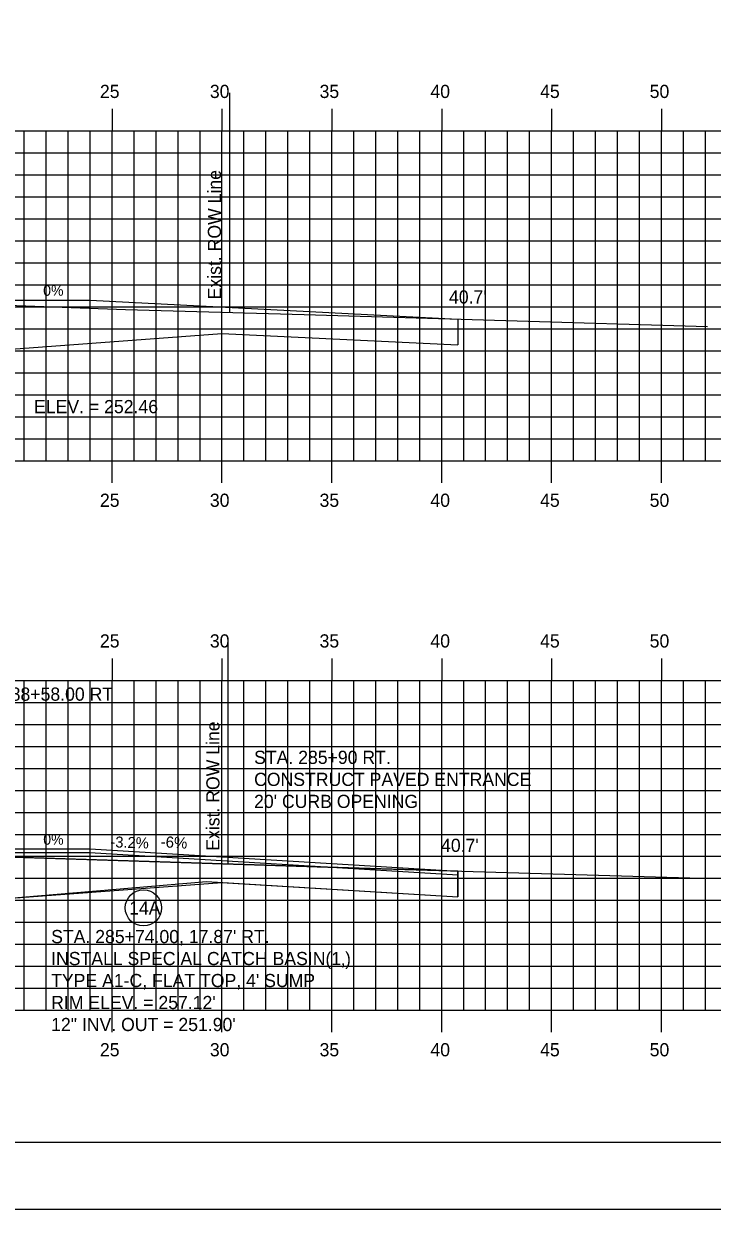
# Model space of a CAD drawing. Extents: x 856903 to 857073, y 366268 to 366378.
# Drawn here: x 857006.8 to 857038.1, y 366268.2 to 366322.1 of the extents above; entities that cross this region are included whole.
import ezdxf

# ---------------------------------------------------------------- set-up
doc = ezdxf.new("R2010")
doc.units = 0
for name, color, linetype in [('ANNOTATION', 7, 'Continuous'), ('BORDER', 7, 'Continuous'), ('D_Drainage_Text', 7, 'Continuous'), ('D_Roadway_Drive_Gravel_LT', 7, 'Continuous'), ('D_Roadway_Drive_Gravel_RT', 7, 'Continuous'), ('D_Roadway_Drive_SubGrade', 7, 'Continuous'), ('D_Text_Monospaced', 7, 'Continuous'), ('D_Text_Standard', 7, 'Continuous'), ('E_ROW_Line', 7, 'Continuous'), ('H_V ANNOTATION', 7, 'Continuous'), ('JUNK COM EXC', 7, 'Continuous'), ('MAJOR', 7, 'Continuous'), ('MINOR', 7, 'Continuous'), ('PLOT BOUNDARY', 7, 'Continuous'), ('S_Roadway_Centerline', 7, 'Continuous')]:
    doc.layers.add(name, color=color, linetype=linetype)

msp = doc.modelspace()

# ---------------------------------------------------------------- linework, layer by layer
at = {"layer": 'BORDER'}
msp.add_line((856910.784, 366271.236), (857070.784, 366271.236), dxfattribs=at)
at = {"layer": 'D_Drainage_Text'}
msp.add_circle((857012.208, 366281.891), 0.825, dxfattribs=at)
at = {"layer": 'D_Roadway_Drive_Gravel_LT'}
for p, q in [((857005.781, 366309.546), (857009.781, 366309.546)), ((857009.781, 366309.546), (857026.513, 366308.678)), ((857015.784, 366308.025), (857026.513, 366307.511)), ((857005.785, 366284.571), (857009.785, 366284.571)), ((857005.785, 366284.404), (857009.785, 366284.404)), ((857009.775, 366284.404), (857026.517, 366283.4)), ((857009.785, 366284.571), (857026.517, 366283.567)), ((857015.784, 366283.042), (857026.517, 366282.398))]:
    msp.add_line(p, q, dxfattribs=at)
at = {"layer": 'D_Roadway_Drive_SubGrade'}
for p, q in [((857026.513, 366308.678), (857026.513, 366307.511)), ((857005.781, 366307.272), (857015.784, 366308.025)), ((857005.784, 366282.297), (857015.784, 366283.042)), ((857026.517, 366283.567), (857026.517, 366282.4))]:
    msp.add_line(p, q, dxfattribs=at)
at = {"layer": 'E_ROW_Line'}
for p, q in [((857016.141, 366308.975), (857016.141, 366318.975)), ((857016.071, 366283.889), (857016.071, 366293.889))]:
    msp.add_line(p, q, dxfattribs=at)
at = {"layer": 'JUNK COM EXC'}
msp.add_lwpolyline([(857005.784, 366284.218), (857005.784, 366282.297), (857005.784, 366282.297), (857015.079, 366283.084), (857026.517, 366282.398), (857026.517, 366283.567), (857022.035, 366283.697), (857005.784, 366284.218)], dxfattribs=at)
at = {"layer": 'MAJOR'}
for p, q in [((857010.784, 366318.238), (857010.784, 366317.236)), ((857015.784, 366318.238), (857015.784, 366317.236)), ((857020.784, 366318.238), (857020.784, 366317.236)), ((857025.784, 366318.238), (857025.784, 366317.236)), ((857030.784, 366318.238), (857030.784, 366317.236)), ((857035.784, 366318.238), (857035.784, 366317.236)), ((856915.784, 366317.236), (857055.784, 366317.236)), ((856915.784, 366317.236), (857055.784, 366317.236)), ((857010.784, 366302.236), (857010.784, 366317.236)), ((857015.784, 366302.236), (857015.784, 366317.236)), ((857020.784, 366302.236), (857020.784, 366317.236)), ((857025.784, 366302.236), (857025.784, 366317.236)), ((857030.784, 366302.236), (857030.784, 366317.236)), ((857035.784, 366302.236), (857035.784, 366317.236)), ((856915.784, 366312.236), (857055.784, 366312.236)), ((856915.784, 366307.236), (857055.784, 366307.236)), ((856915.784, 366302.236), (857055.784, 366302.236)), ((856915.784, 366302.236), (857055.784, 366302.236)), ((857010.784, 366301.234), (857010.784, 366302.236)), ((857015.784, 366301.234), (857015.784, 366302.236)), ((857020.784, 366301.234), (857020.784, 366302.236)), ((857025.784, 366301.234), (857025.784, 366302.236)), ((857030.784, 366301.234), (857030.784, 366302.236)), ((857035.784, 366301.234), (857035.784, 366302.236)), ((857010.784, 366293.238), (857010.784, 366292.236)), ((857015.784, 366293.238), (857015.784, 366292.236)), ((857020.784, 366293.238), (857020.784, 366292.236)), ((857025.784, 366293.238), (857025.784, 366292.236)), ((857030.784, 366293.238), (857030.784, 366292.236)), ((857035.784, 366293.238), (857035.784, 366292.236)), ((856915.784, 366292.236), (857055.784, 366292.236)), ((856915.784, 366292.236), (857055.784, 366292.236)), ((857010.784, 366277.236), (857010.784, 366292.236)), ((857015.784, 366277.236), (857015.784, 366292.236)), ((857020.784, 366277.236), (857020.784, 366292.236)), ((857025.784, 366277.236), (857025.784, 366292.236)), ((857030.784, 366277.236), (857030.784, 366292.236)), ((857035.784, 366277.236), (857035.784, 366292.236)), ((856915.784, 366287.236), (857055.784, 366287.236)), ((856915.784, 366282.236), (857055.784, 366282.236)), ((856915.784, 366277.236), (857055.784, 366277.236)), ((856915.784, 366277.236), (857055.784, 366277.236)), ((857010.784, 366276.234), (857010.784, 366277.236)), ((857015.784, 366276.234), (857015.784, 366277.236)), ((857020.784, 366276.234), (857020.784, 366277.236)), ((857025.784, 366276.234), (857025.784, 366277.236)), ((857030.784, 366276.234), (857030.784, 366277.236)), ((857035.784, 366276.234), (857035.784, 366277.236))]:
    msp.add_line(p, q, dxfattribs=at)
at = {"layer": 'MINOR'}
for p, q in [((857006.784, 366302.236), (857006.784, 366317.236)), ((857007.784, 366302.236), (857007.784, 366317.236)), ((857008.784, 366302.236), (857008.784, 366317.236)), ((857009.784, 366302.236), (857009.784, 366317.236)), ((857011.784, 366302.236), (857011.784, 366317.236)), ((857012.784, 366302.236), (857012.784, 366317.236)), ((857013.784, 366302.236), (857013.784, 366317.236)), ((857014.784, 366302.236), (857014.784, 366317.236)), ((857016.784, 366302.236), (857016.784, 366317.236)), ((857017.784, 366302.236), (857017.784, 366317.236)), ((857018.784, 366302.236), (857018.784, 366317.236)), ((857019.784, 366302.236), (857019.784, 366317.236)), ((857021.784, 366302.236), (857021.784, 366317.236)), ((857022.784, 366302.236), (857022.784, 366317.236)), ((857023.784, 366302.236), (857023.784, 366317.236)), ((857024.784, 366302.236), (857024.784, 366317.236)), ((857026.784, 366302.236), (857026.784, 366317.236)), ((857027.784, 366302.236), (857027.784, 366317.236)), ((857028.784, 366302.236), (857028.784, 366317.236)), ((857029.784, 366302.236), (857029.784, 366317.236)), ((857031.784, 366302.236), (857031.784, 366317.236)), ((857032.784, 366302.236), (857032.784, 366317.236)), ((857033.784, 366302.236), (857033.784, 366317.236)), ((857034.784, 366302.236), (857034.784, 366317.236)), ((857036.784, 366302.236), (857036.784, 366317.236)), ((857037.784, 366302.236), (857037.784, 366317.236)), ((856915.784, 366316.236), (857055.784, 366316.236)), ((856915.784, 366315.236), (857055.784, 366315.236)), ((856915.784, 366314.236), (857055.784, 366314.236)), ((856915.784, 366313.236), (857055.784, 366313.236)), ((856915.784, 366311.236), (857055.784, 366311.236)), ((856915.784, 366310.236), (857055.784, 366310.236)), ((856915.784, 366309.236), (857055.784, 366309.236)), ((856915.784, 366308.236), (857055.784, 366308.236)), ((856915.784, 366306.236), (857055.784, 366306.236)), ((856915.784, 366305.236), (857055.784, 366305.236)), ((856915.784, 366304.236), (857055.784, 366304.236)), ((856915.784, 366303.236), (857055.784, 366303.236)), ((857006.784, 366277.236), (857006.784, 366292.236)), ((857007.784, 366277.236), (857007.784, 366292.236)), ((857008.784, 366277.236), (857008.784, 366292.236)), ((857009.784, 366277.236), (857009.784, 366292.236)), ((857011.784, 366277.236), (857011.784, 366292.236)), ((857012.784, 366277.236), (857012.784, 366292.236)), ((857013.784, 366277.236), (857013.784, 366292.236)), ((857014.784, 366277.236), (857014.784, 366292.236)), ((857016.784, 366277.236), (857016.784, 366292.236)), ((857017.784, 366277.236), (857017.784, 366292.236)), ((857018.784, 366277.236), (857018.784, 366292.236)), ((857019.784, 366277.236), (857019.784, 366292.236)), ((857021.784, 366277.236), (857021.784, 366292.236)), ((857022.784, 366277.236), (857022.784, 366292.236)), ((857023.784, 366277.236), (857023.784, 366292.236)), ((857024.784, 366277.236), (857024.784, 366292.236)), ((857026.784, 366277.236), (857026.784, 366292.236)), ((857027.784, 366277.236), (857027.784, 366292.236)), ((857028.784, 366277.236), (857028.784, 366292.236)), ((857029.784, 366277.236), (857029.784, 366292.236)), ((857031.784, 366277.236), (857031.784, 366292.236)), ((857032.784, 366277.236), (857032.784, 366292.236)), ((857033.784, 366277.236), (857033.784, 366292.236)), ((857034.784, 366277.236), (857034.784, 366292.236)), ((857036.784, 366277.236), (857036.784, 366292.236)), ((857037.784, 366277.236), (857037.784, 366292.236)), ((856915.784, 366291.236), (857055.784, 366291.236)), ((856915.784, 366290.236), (857055.784, 366290.236)), ((856915.784, 366289.236), (857055.784, 366289.236)), ((856915.784, 366288.236), (857055.784, 366288.236)), ((856915.784, 366286.236), (857055.784, 366286.236)), ((856915.784, 366285.236), (857055.784, 366285.236)), ((856915.784, 366284.236), (857055.784, 366284.236)), ((856915.784, 366283.236), (857055.784, 366283.236)), ((856915.784, 366281.236), (857055.784, 366281.236)), ((856915.784, 366280.236), (857055.784, 366280.236)), ((856915.784, 366279.236), (857055.784, 366279.236)), ((856915.784, 366278.236), (857055.784, 366278.236))]:
    msp.add_line(p, q, dxfattribs=at)
at = {"layer": 'PLOT BOUNDARY'}
msp.add_lwpolyline([(856902.691, 366268.177), (857072.691, 366268.177), (857072.691, 366378.177), (856902.691, 366378.177)], close=True, dxfattribs=at)
at = {"layer": 'S_Roadway_Centerline'}
for points in [[(856967.725, 366309.157), (856971.171, 366309.335), (856975.751, 366309.678), (856980.618, 366309.765), (856985.933, 366309.959), (856991.679, 366309.628), (856996.749, 366309.39), (857000.171, 366309.291), (857002.68, 366309.2), (857002.698, 366309.225), (857004.597, 366309.268), (857004.879, 366309.319), (857005.591, 366309.325), (857011.392, 366309.107), (857019.528, 366308.881), (857037.887, 366308.346)], [(856928.638, 366284.466), (856941.425, 366284.86), (856945.596, 366284.966), (856952.237, 366285.026), (856963.162, 366284.875), (856963.518, 366284.787), (856963.712, 366284.697), (856965.326, 366284.666), (856967.014, 366284.586), (856967.196, 366284.361), (856967.593, 366284.051), (856969.584, 366284.154), (856975.753, 366284.616), (856978.579, 366284.666), (856985.947, 366284.936), (856993.912, 366284.477), (856996.656, 366284.348), (857001.427, 366284.21), (857002.776, 366284.161), (857002.786, 366284.174), (857004.302, 366284.209), (857005.32, 366284.233), (857022.035, 366283.697), (857037.595, 366283.244)]]:
    msp.add_lwpolyline(points, dxfattribs=at)

# ---------------------------------------------------------------- texts
at = {"layer": 'ANNOTATION'}
for s, p in [('STA. 285+90 RT.', (857017.246, 366288.439)), ('CONSTRUCT PAVED ENTRANCE', (857017.246, 366287.437)), ("20' CURB OPENING", (857017.246, 366286.435))]:
    msp.add_text(s, height=0.6, dxfattribs=at).set_placement(p)
msp.add_text('-6%', height=0.51, rotation=356.5664, dxfattribs=at).set_placement((857012.981, 366284.654))
at = {"layer": 'D_Drainage_Text'}
for s, p in [('STA. 285+79.00 TO STA. 288+58.00 RT', (856996.334, 366291.315)), ("STA. 285+74.00, 17.87' RT.", (857008.009, 366280.285)), ('INSTALL SPECIAL CATCH BASIN(1‚)', (857008.009, 366279.285)), ("TYPE A1-C, FLAT TOP, 4' SUMP", (857008.009, 366278.285)), ("RIM ELEV. = 257.12'", (857008.009, 366277.285)), ('12" INV. OUT = 251.90\'', (857008.009, 366276.285))]:
    msp.add_text(s, height=0.6, dxfattribs=at).set_placement(p)
at = {"layer": 'D_Roadway_Drive_Gravel_RT'}
for p in [(857007.646, 366309.739), (857007.65, 366284.764)]:
    msp.add_text('0%', height=0.48, dxfattribs=at).set_placement(p)
at = {"layer": 'D_Text_Monospaced'}
msp.add_text('-3.2%', height=0.5, rotation=358.0425, dxfattribs=at).set_placement((857010.7, 366284.648))
at = {"layer": 'D_Text_Standard'}
for s, p in [("40.7'", (857026.116, 366309.385)), ('ELEV. = 252.46', (857007.231, 366304.396)), ("40.7'", (857025.754, 366284.436))]:
    msp.add_text(s, height=0.6, dxfattribs=at).set_placement(p)
at = {"layer": 'E_ROW_Line'}
for p in [(857015.741, 366309.575), (857015.671, 366284.489)]:
    msp.add_text('Exist. ROW Line', height=0.6, rotation=90, dxfattribs=at).set_placement(p)
at = {"layer": 'H_V ANNOTATION'}
for s, p in [('25', (857010.23, 366318.736)), ('30', (857015.233, 366318.736)), ('35', (857020.225, 366318.736)), ('40', (857025.27, 366318.736)), ('45', (857030.262, 366318.736)), ('50', (857035.249, 366318.736)), ('25', (857010.23, 366300.136)), ('30', (857015.233, 366300.136)), ('35', (857020.225, 366300.136)), ('40', (857025.27, 366300.136)), ('45', (857030.262, 366300.136)), ('50', (857035.249, 366300.136)), ('25', (857010.23, 366293.736)), ('30', (857015.233, 366293.736)), ('35', (857020.225, 366293.736)), ('40', (857025.27, 366293.736)), ('45', (857030.262, 366293.736)), ('50', (857035.249, 366293.736)), ('14A', (857011.56, 366281.587)), ('25', (857010.23, 366275.136)), ('30', (857015.233, 366275.136)), ('35', (857020.225, 366275.136)), ('40', (857025.27, 366275.136)), ('45', (857030.262, 366275.136)), ('50', (857035.249, 366275.136))]:
    msp.add_text(s, height=0.6, dxfattribs=at).set_placement(p)

doc.saveas('drawing.dxf')
